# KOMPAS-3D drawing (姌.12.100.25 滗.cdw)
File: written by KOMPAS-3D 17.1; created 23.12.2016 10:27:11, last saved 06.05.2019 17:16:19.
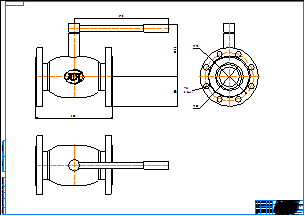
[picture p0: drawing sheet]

Sheet 1: A0, landscape

Title block, sheet 1: name: КШ.12.100.25 фф; material: Внимание! Данный продукт является объектом авторского права ООО «Торговый Дом АДЛ». / Запрещается изменение, копирование, распространение / (в том числе путем копирования на другие сайты и ресурсы в Интернете) / или любое иное использование информации и объектов без предварительного / согласия правообладателя (ООО «Торговый Дом АДЛ»).; sheets: 1; organisation: ООО "Торговый дом АДЛ"; sheet format: A0; stored path: C:\Users\tra\Desktop\2д чертежи\Шаровые краны БИВАЛ\КШ_Бивал_серия_11_12\KOMPAS_2D\КШ.12.100.25 фф.cdw

Views: Вид 1, Проекционный вид 2, Проекционный вид 3
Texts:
  Klimkovich
  ADL
Dimensions and other numbers on the sheet: 300; 370; 205,1; 115; 190; 100; 22; 8 Отв.; 1:1; 1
